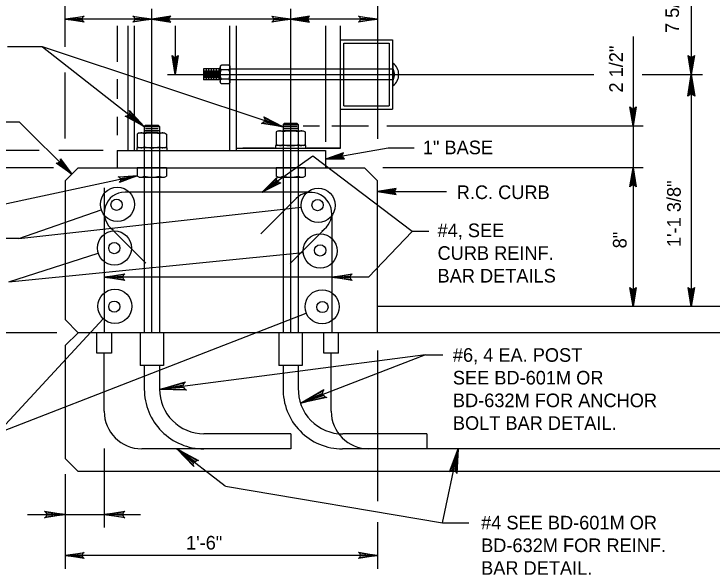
# Model space of a CAD drawing. Extents: x 641054 to 641910, y 298137 to 299325.
# Drawn here: x 641174.5 to 641328.5, y 298785.6 to 298908.1 of the extents above; entities that cross this region are included whole.
import ezdxf

# ---------------------------------------------------------------- set-up
doc = ezdxf.new("R2010")
doc.units = 0
for name, color, linetype in [('1', 7, 'Continuous'), ('2', 7, 'Continuous'), ('3', 7, 'Continuous'), ('4', 7, 'Continuous'), ('S-STEL', 7, 'Continuous')]:
    doc.layers.add(name, color=color, linetype=linetype)

msp = doc.modelspace()

# ---------------------------------------------------------------- linework, layer by layer
at = {"layer": '1'}
for p, q in [((641323.89, 298981.43), (641323.89, 298843.61)), ((641185.81, 298900.89), (641185.81, 298948.15)), ((641254.66, 298939.43), (641254.66, 298880.61)), ((641254.66, 298906.98), (641185.81, 298906.98)), ((641197.28, 298905.47), (641197.28, 298897.55)), ((641210.04, 298905.47), (641210.04, 298894.7)), ((641243.19, 298905.47), (641243.19, 298879.92)), ((641311.04, 298903.12), (641311.04, 298868.53)), ((641180.8, 298900.88), (641173.07, 298900.88)), ((641233.86, 298883.2), (641180.8, 298900.88)), ((641180.8, 298900.88), (641203.26, 298883.3)), ((641221.91, 298896.86), (641220.25, 298896.86)), ((641258.12, 298895.93), (641258.12, 298897.21)), ((641258.14, 298895.93), (641258.14, 298897.21)), ((641185.81, 298880.69), (641185.81, 298895.19)), ((641220.01, 298895.99), (641216.31, 298895.99)), ((641216.31, 298895.99), (641216.31, 298893.6)), ((641216.59, 298895.62), (641216.59, 298893.99)), ((641216.87, 298895.99), (641216.87, 298893.6)), ((641217.15, 298895.62), (641217.15, 298893.99)), ((641217.43, 298895.99), (641217.43, 298893.6)), ((641217.7, 298895.62), (641217.7, 298893.99)), ((641217.98, 298895.99), (641217.98, 298893.6)), ((641218.26, 298895.62), (641218.26, 298893.99)), ((641218.54, 298895.99), (641218.54, 298893.6)), ((641218.82, 298895.62), (641218.82, 298893.99)), ((641219.1, 298895.99), (641219.1, 298893.6)), ((641219.38, 298895.62), (641219.38, 298893.99)), ((641219.66, 298895.99), (641219.66, 298893.6)), ((641219.94, 298895.62), (641219.94, 298893.99)), ((641220.01, 298896.59), (641220.01, 298896.35)), ((641220.01, 298896.35), (641220.01, 298894.79)), ((641221.91, 298895.83), (641220.25, 298895.83)), ((641222.15, 298896.59), (641222.15, 298893)), ((641247.25, 298895.95), (641222.15, 298895.95)), ((641257.29, 298895.95), (641247.25, 298895.95)), ((641258.02, 298895.95), (641257.3, 298895.95)), ((641258.01, 298896.39), (641258.01, 298894.82)), ((641258.12, 298895.93), (641258.14, 298895.93)), ((641258.12, 298895.93), (641258.12, 298893.58)), ((641197.28, 298893.74), (641197.28, 298889.42)), ((641220.01, 298894.79), (641220.01, 298893.24)), ((641221.91, 298893.76), (641220.25, 298893.76)), ((641220.01, 298893.6), (641216.31, 298893.6)), ((641220.01, 298893.24), (641220.01, 298893)), ((641221.91, 298892.72), (641220.25, 298892.72)), ((641247.25, 298893.56), (641222.15, 298893.56)), ((641257.29, 298893.56), (641247.25, 298893.56)), ((641258.02, 298893.56), (641257.3, 298893.56)), ((641258.12, 298892.31), (641258.12, 298893.58)), ((641258.14, 298892.31), (641258.14, 298893.58)), ((641197.28, 298885.46), (641197.28, 298881.38)), ((641175.75, 298884.27), (641171.85, 298884.27)), ((641187.24, 298872.78), (641175.75, 298884.27)), ((641203.26, 298883.3), (641203.54, 298883.58)), ((641203.26, 298883.3), (641203.26, 298881.9)), ((641203.26, 298883.3), (641206.61, 298883.3)), ((641203.53, 298882.88), (641206.34, 298882.88)), ((641203.54, 298883.58), (641206.33, 298883.58)), ((641206.61, 298883.3), (641206.33, 298883.58)), ((641206.61, 298883.3), (641206.61, 298881.9)), ((641233.86, 298883.77), (641234.14, 298884.05)), ((641233.86, 298883.77), (641233.86, 298882.38)), ((641233.86, 298883.77), (641237.21, 298883.77)), ((641233.86, 298882.94), (641237.21, 298882.94)), ((641234.13, 298883.36), (641236.94, 298883.36)), ((641234.14, 298884.05), (641236.93, 298884.05)), ((641237.21, 298883.77), (641236.93, 298884.05)), ((641237.21, 298883.77), (641237.21, 298882.38)), ((641238.3, 298883.48), (641241.88, 298883.48)), ((641244.6, 298883.48), (641252.72, 298883.48)), ((641256.75, 298883.48), (641313.3, 298883.48)), ((641202.15, 298881.9), (641201.71, 298881.65)), ((641201.71, 298881.65), (641201.71, 298878.86)), ((641202.15, 298881.9), (641207.72, 298881.9)), ((641203.26, 298882.46), (641206.61, 298882.46)), ((641203.26, 298882.38), (641203.26, 298837.87)), ((641203.26, 298881.66), (641203.26, 298878.85)), ((641203.53, 298882.04), (641206.34, 298882.04)), ((641206.61, 298882.38), (641206.61, 298837.87)), ((641206.61, 298881.66), (641206.61, 298878.86)), ((641207.72, 298881.9), (641208.16, 298881.65)), ((641208.16, 298881.65), (641208.16, 298878.86)), ((641232.75, 298882.38), (641232.32, 298882.13)), ((641232.32, 298882.13), (641232.32, 298879.34)), ((641232.75, 298882.38), (641238.33, 298882.38)), ((641233.86, 298882.38), (641233.86, 298837.87)), ((641233.86, 298882.14), (641233.86, 298879.33)), ((641234.13, 298882.52), (641236.94, 298882.52)), ((641237.21, 298882.38), (641237.21, 298837.87)), ((641237.21, 298882.14), (641237.21, 298879.34)), ((641238.33, 298882.38), (641238.76, 298882.13)), ((641238.76, 298882.13), (641238.76, 298879.34)), ((641202.15, 298878.61), (641201.71, 298878.86)), ((641207.72, 298878.61), (641208.16, 298878.86)), ((641232.75, 298879.09), (641232.32, 298879.34)), ((641238.33, 298879.09), (641238.76, 298879.34)), ((641257.03, 298878.52), (641243.19, 298876.13)), ((641262.77, 298878.52), (641257.03, 298878.52)), ((641180.09, 298878.04), (641168.79, 298878.04)), ((641194.18, 298878.04), (641184.37, 298878.04)), ((641183.24, 298874.22), (641168.79, 298874.22)), ((641201.71, 298874.21), (641201.71, 298872.37)), ((641208.16, 298874.21), (641201.71, 298874.21)), ((641203.26, 298874.21), (641203.26, 298872.37)), ((641206.61, 298874.21), (641206.61, 298872.37)), ((641208.16, 298874.21), (641208.16, 298872.37)), ((641232.32, 298874.22), (641232.32, 298872.37)), ((641238.76, 298874.22), (641232.32, 298874.22)), ((641233.86, 298874.22), (641233.86, 298872.37)), ((641237.21, 298874.22), (641237.21, 298872.37)), ((641238.76, 298874.22), (641238.76, 298872.37)), ((641313.3, 298874.22), (641255.88, 298874.22)), ((641311.04, 298874.22), (641311.04, 298843.61)), ((641201.71, 298872.47), (641164.04, 298864.39)), ((641202.15, 298872.12), (641201.71, 298872.37)), ((641202.15, 298872.12), (641207.72, 298872.12)), ((641207.72, 298872.12), (641208.16, 298872.37)), ((641232.75, 298872.12), (641232.32, 298872.37)), ((641232.75, 298872.12), (641238.33, 298872.12)), ((641238.33, 298872.12), (641238.76, 298872.37)), ((641254.66, 298868.96), (641269.92, 298868.96)), ((641183.99, 298837.87), (641169.06, 298837.87)), ((641254.66, 298833.93), (641254.66, 298800.72)), ((641203.26, 298830.61), (641203.26, 298825.43)), ((641206.61, 298830.61), (641206.61, 298825.43)), ((641233.86, 298830.61), (641233.86, 298825.67)), ((641237.21, 298830.61), (641237.21, 298825.66)), ((641235.58, 298815.61), (641216.39, 298815.61)), ((641235.58, 298815.61), (641235.58, 298812.27)), ((641265.58, 298815.55), (641247.05, 298815.55)), ((641265.58, 298815.55), (641265.58, 298812.27)), ((641235.58, 298812.27), (641216.39, 298812.27)), ((641265.58, 298812.27), (641246.99, 298812.27)), ((641185.81, 298806.72), (641185.81, 298785.83)), ((641254.66, 298796.11), (641254.66, 298785.83)), ((641254.66, 298788.78), (641185.81, 298788.78))]:
    msp.add_line(p, q, dxfattribs=at)
msp.add_lwpolyline([(641323.32, 298890.23), (641323.65, 298890.4), (641323.89, 298894.78), (641323.32, 298890.23), (641323.12, 298890), (641323.89, 298894.78), (641324.11, 298890.41), (641324.44, 298890.25), (641323.89, 298894.78), (641324.65, 298890), (641324.44, 298890.25)], dxfattribs=at)
for points in [[(641208.28, 298878.04), (641208.28, 298878.61), (641201.59, 298878.61), (641201.59, 298878.04)], [(641238.89, 298878.52), (641238.89, 298879.09), (641232.19, 298879.09), (641232.19, 298878.52)]]:
    msp.add_lwpolyline(points, close=True, dxfattribs=at)
for centre, radius, start, end in [((641256.33, 298894.76), 3.04, 306.3703, 53.6297), ((641258, 298896.07), 0.119, 272.7217, 0.0027), ((641256.33, 298894.76), 2.15, 326.9318, 33.0682), ((641258, 298893.44), 0.119, 359.9973, 87.2783), ((641202.49, 298880.58), 1.33, 54.2974, 89.9999), ((641204.93, 298876.16), 5.75, 73.0653, 106.9335), ((641207.38, 298880.58), 1.33, 89.9993, 125.7017), ((641233.09, 298881.05), 1.33, 54.2974, 89.9999), ((641235.54, 298876.63), 5.75, 73.0653, 106.9335), ((641237.99, 298881.05), 1.33, 89.9993, 125.7017), ((641202.49, 298879.94), 1.33, 269.9985, 305.701), ((641204.93, 298884.36), 5.75, 253.0634, 286.9317), ((641207.38, 298879.94), 1.33, 234.2959, 269.9983), ((641233.09, 298880.42), 1.33, 269.9985, 305.701), ((641235.54, 298884.84), 5.75, 253.0634, 286.9317), ((641237.99, 298880.42), 1.33, 234.2959, 269.9983), ((641202.49, 298873.45), 1.33, 269.9985, 305.701), ((641204.93, 298877.87), 5.75, 253.0634, 286.9317), ((641207.38, 298873.45), 1.33, 234.2959, 269.9983), ((641233.09, 298873.45), 1.33, 269.9985, 305.701), ((641235.54, 298877.87), 5.75, 253.0634, 286.9317), ((641237.99, 298873.45), 1.33, 234.2959, 269.9983), ((641216.39, 298825.39), 13.13, 179.7931, 270), ((641216.39, 298825.39), 9.78, 179.7931, 270), ((641246.99, 298825.39), 13.13, 178.7837, 270), ((641247.05, 298825.39), 9.84, 178.4167, 270)]:
    msp.add_arc(centre, radius, start, end, dxfattribs=at)
for points, degree in [([(641220.01, 298896.35), (641220.02, 298896.42), (641220.04, 298896.58), (641220.15, 298896.74), (641220.23, 298896.83), (641220.25, 298896.86)], 3), ([(641220.01, 298896.59), (641220.25, 298896.86)], 1), ([(641222.15, 298896.35), (641222.14, 298896.42), (641222.12, 298896.58), (641222.01, 298896.74), (641221.93, 298896.83), (641221.91, 298896.86)], 3), ([(641221.91, 298896.86), (641222.15, 298896.59)], 1), ([(641220.25, 298895.83), (641220.19, 298895.91), (641220.07, 298896.06), (641220.01, 298896.25), (641220.01, 298896.34), (641220.01, 298896.35)], 3), ([(641220.01, 298894.79), (641220.01, 298894.82), (641220.02, 298894.97), (641220.05, 298895.26), (641220.15, 298895.58), (641220.23, 298895.77), (641220.25, 298895.83)], 3), ([(641221.91, 298895.83), (641221.97, 298895.91), (641222.09, 298896.06), (641222.15, 298896.25), (641222.15, 298896.34), (641222.15, 298896.35)], 3), ([(641222.15, 298894.79), (641222.15, 298894.82), (641222.15, 298894.97), (641222.11, 298895.26), (641222.01, 298895.58), (641221.94, 298895.77), (641221.91, 298895.83)], 3), ([(641222.15, 298895.99), (641222.15, 298895.99)], 1), ([(641258, 298895.95), (641258, 298895.95), (641258.03, 298895.95), (641258.1, 298895.94), (641258.11, 298895.89), (641258.12, 298895.87)], 3), ([(641258, 298895.95), (641258, 298895.95)], 1), ([(641220.25, 298893.76), (641220.22, 298893.84), (641220.13, 298894.05), (641220.04, 298894.4), (641220.02, 298894.66), (641220.01, 298894.79)], 3), ([(641220.01, 298893.24), (641220.02, 298893.31), (641220.04, 298893.47), (641220.15, 298893.64), (641220.23, 298893.73), (641220.25, 298893.76)], 3), ([(641221.91, 298893.76), (641221.95, 298893.84), (641222.03, 298894.05), (641222.13, 298894.4), (641222.14, 298894.66), (641222.15, 298894.79)], 3), ([(641222.15, 298893.24), (641222.14, 298893.31), (641222.12, 298893.47), (641222.01, 298893.64), (641221.93, 298893.73), (641221.91, 298893.76)], 3), ([(641258.12, 298893.65), (641258.11, 298893.63), (641258.1, 298893.58), (641258.03, 298893.56), (641258, 298893.56), (641258, 298893.56)], 3), ([(641220.25, 298892.72), (641220.19, 298892.8), (641220.07, 298892.95), (641220.01, 298893.14), (641220.01, 298893.24), (641220.01, 298893.24)], 3), ([(641220.25, 298892.72), (641220.01, 298893)], 1), ([(641221.91, 298892.72), (641221.97, 298892.8), (641222.09, 298892.95), (641222.15, 298893.14), (641222.15, 298893.24), (641222.15, 298893.24)], 3), ([(641222.15, 298893), (641221.91, 298892.72)], 1), ([(641222.15, 298893.6), (641222.15, 298893.6)], 1)]:
    msp.add_open_spline(points, degree=degree, dxfattribs=at)
at = {"layer": '2'}
for p, q in [((641204.93, 298837.87), (641204.93, 298909.25)), ((641235.54, 298837.87), (641235.54, 298909.25)), ((641199.67, 298878.04), (641199.67, 298905.47)), ((641201.11, 298878.04), (641201.11, 298905.47)), ((641222.14, 298878.04), (641222.14, 298905.47)), ((641223.58, 298878.04), (641223.58, 298905.47)), ((641246.53, 298878.52), (641246.53, 298905.47)), ((641246.53, 298902.42), (641258.01, 298902.42)), ((641247.25, 298887.84), (641247.25, 298901.71)), ((641247.25, 298901.71), (641257.29, 298901.71)), ((641257.29, 298901.71), (641257.29, 298887.84)), ((641258.01, 298902.42), (641258.01, 298887.12)), ((641208.34, 298894.78), (641302.41, 298894.78)), ((641313.04, 298894.78), (641326.35, 298894.78)), ((641247.25, 298887.84), (641257.29, 298887.84)), ((641246.53, 298887.12), (641258.01, 298887.12)), ((641223.58, 298878.52), (641246.53, 298878.52)), ((641246.53, 298878.52), (641239.12, 298878.52)), ((641197.28, 298878.04), (641243.19, 298878.04)), ((641197.28, 298878.04), (641197.28, 298874.22)), ((641243.19, 298878.04), (641243.19, 298874.22)), ((641185.81, 298871.35), (641188.68, 298874.22)), ((641188.68, 298874.22), (641251.8, 298874.22)), ((641254.66, 298871.35), (641251.8, 298874.22)), ((641185.81, 298871.35), (641185.81, 298840.74)), ((641254.66, 298837.87), (641254.66, 298871.35)), ((641175.55, 298858.64), (641237.87, 298865.52)), ((641175.55, 298858.64), (641193.76, 298864.92)), ((641252.67, 298850.1), (641262.33, 298860.18)), ((641265.99, 298860.18), (641262.33, 298860.18)), ((641175.55, 298858.64), (641169.48, 298858.64)), ((641173.4, 298849.09), (641238.3, 298855.51)), ((641173.4, 298849.09), (641193.08, 298855.38)), ((641252.67, 298850.1), (641194.42, 298850.1)), ((641369.97, 298843.61), (641254.66, 298843.61)), ((641170.83, 298815.69), (641238.97, 298842.2)), ((641170.83, 298815.69), (641194.22, 298840.92)), ((641188.68, 298837.87), (641185.81, 298840.74)), ((641185.81, 298835.01), (641188.68, 298837.87)), ((641369.97, 298837.87), (641188.68, 298837.87)), ((641202.32, 298837.87), (641202.32, 298830.61)), ((641207.48, 298837.87), (641202.32, 298837.87)), ((641207.48, 298837.87), (641207.48, 298830.61)), ((641232.93, 298837.87), (641232.93, 298830.61)), ((641238.08, 298837.87), (641232.93, 298837.87)), ((641238.08, 298837.87), (641238.08, 298830.61)), ((641185.81, 298835.01), (641185.81, 298810.14)), ((641265.24, 298832.95), (641206.61, 298825.36)), ((641265.24, 298832.95), (641237.7, 298822.32)), ((641265.24, 298832.95), (641269.1, 298832.95)), ((641207.48, 298830.61), (641202.32, 298830.61)), ((641238.08, 298830.61), (641232.93, 298830.61)), ((641194.42, 298812.35), (641194.42, 298794.92)), ((641221.11, 298804.05), (641210.4, 298812.27)), ((641269, 298795.95), (641272.48, 298812.27)), ((641188.68, 298807.27), (641185.81, 298810.14)), ((641369.97, 298807.27), (641188.68, 298807.27)), ((641177.47, 298797.78), (641185.81, 298797.78)), ((641185.81, 298797.78), (641194.42, 298797.78)), ((641194.42, 298797.78), (641202.42, 298797.78))]:
    msp.add_line(p, q, dxfattribs=at)
for points in [[(641189.78, 298906.49), (641189.63, 298906.77), (641185.81, 298906.98), (641189.78, 298906.49), (641189.98, 298906.31), (641185.81, 298906.98), (641189.63, 298907.17), (641189.77, 298907.46), (641185.81, 298906.98), (641189.98, 298907.65), (641189.77, 298907.46)], [(641200.96, 298907.48), (641201.11, 298907.2), (641204.93, 298906.98), (641200.96, 298907.48), (641200.76, 298907.66), (641204.93, 298906.98), (641201.11, 298906.8), (641200.97, 298906.51), (641204.93, 298906.98), (641200.76, 298906.32), (641200.97, 298906.51)], [(641208.91, 298907.48), (641208.76, 298907.2), (641204.93, 298906.98), (641208.91, 298907.48), (641209.11, 298907.66), (641204.93, 298906.98), (641208.76, 298906.8), (641208.9, 298906.51), (641204.93, 298906.98), (641209.11, 298906.32), (641208.9, 298906.51)], [(641231.56, 298907.48), (641231.71, 298907.2), (641235.54, 298906.98), (641231.56, 298907.48), (641231.36, 298907.66), (641235.54, 298906.98), (641231.72, 298906.8), (641231.58, 298906.51), (641235.54, 298906.98), (641231.36, 298906.32), (641231.58, 298906.51)], [(641239.51, 298907.48), (641239.36, 298907.2), (641235.54, 298906.98), (641239.51, 298907.48), (641239.71, 298907.66), (641235.54, 298906.98), (641239.36, 298906.8), (641239.5, 298906.51), (641235.54, 298906.98), (641239.71, 298906.32), (641239.5, 298906.51)], [(641250.69, 298907.48), (641250.84, 298907.2), (641254.66, 298906.98), (641250.69, 298907.48), (641250.49, 298907.66), (641254.66, 298906.98), (641250.84, 298906.8), (641250.7, 298906.51), (641254.66, 298906.98), (641250.49, 298906.32), (641250.7, 298906.51)], [(641210.54, 298898.75), (641210.25, 298898.6), (641210.04, 298894.78), (641210.54, 298898.75), (641210.71, 298898.95), (641210.04, 298894.78), (641209.85, 298898.6), (641209.57, 298898.74), (641210.04, 298894.78), (641209.38, 298898.95), (641209.57, 298898.74)], [(641324.39, 298898.75), (641324.11, 298898.6), (641323.89, 298894.78), (641324.39, 298898.75), (641324.57, 298898.95), (641323.89, 298894.78), (641323.71, 298898.6), (641323.42, 298898.74), (641323.89, 298894.78), (641323.23, 298898.95), (641323.42, 298898.74)], [(641311.54, 298887.45), (641311.25, 298887.3), (641311.04, 298883.48), (641311.54, 298887.45), (641311.71, 298887.66), (641311.04, 298883.48), (641310.85, 298887.3), (641310.57, 298887.44), (641311.04, 298883.48), (641310.37, 298887.66), (641310.57, 298887.44)], [(641200.05, 298886.51), (641199.99, 298886.15), (641203.26, 298883.3), (641200.05, 298886.51), (641199.99, 298886.81), (641203.26, 298883.3), (641199.71, 298885.79), (641199.39, 298885.63), (641203.26, 298883.3), (641199.06, 298885.61), (641199.39, 298885.63)], [(641229.77, 298885.16), (641229.83, 298884.8), (641233.86, 298883.2), (641229.77, 298885.16), (641229.61, 298885.42), (641233.86, 298883.2), (641229.69, 298884.37), (641229.43, 298884.11), (641233.86, 298883.2), (641229.14, 298883.98), (641229.43, 298884.11)], [(641262.33, 298860.18), (641240.41, 298876.78), (641229.24, 298868.86)], [(641247.02, 298877.3), (641246.92, 298876.99), (641243.19, 298876.13), (641247.02, 298877.3), (641247.19, 298877.5), (641243.19, 298876.13), (641246.99, 298876.59), (641247.17, 298876.34), (641243.19, 298876.13), (641247.42, 298876.18), (641247.17, 298876.34)], [(641184.78, 298875.94), (641184.69, 298875.63), (641187.24, 298872.78), (641184.78, 298875.94), (641184.76, 298876.21), (641187.24, 298872.78), (641184.41, 298875.35), (641184.11, 298875.25), (641187.24, 298872.78), (641183.82, 298875.26), (641184.11, 298875.25)], [(641310.54, 298870.24), (641310.83, 298870.39), (641311.04, 298874.22), (641310.54, 298870.24), (641310.37, 298870.04), (641311.04, 298874.22), (641311.23, 298870.39), (641311.51, 298870.25), (641311.04, 298874.22), (641311.7, 298870.04), (641311.51, 298870.25)], [(641197.72, 298872.12), (641197.93, 298871.87), (641201.71, 298872.47), (641197.72, 298872.12), (641197.49, 298872.25), (641201.71, 298872.47), (641198.02, 298871.48), (641197.94, 298871.17), (641201.71, 298872.47), (641197.77, 298870.94), (641197.94, 298871.17)], [(641233.06, 298870.93), (641232.75, 298871.09), (641229.24, 298868.86), (641233.06, 298870.93), (641233.35, 298870.91), (641229.24, 298868.86), (641232.5, 298871.44), (641232.44, 298871.78), (641229.24, 298868.86), (641232.51, 298872.09), (641232.44, 298871.78)], [(641258.64, 298869.46), (641258.49, 298869.17), (641254.66, 298868.96), (641258.64, 298869.46), (641258.84, 298869.63), (641254.66, 298868.96), (641258.49, 298868.77), (641258.63, 298868.48), (641254.66, 298868.96), (641258.84, 298868.29), (641258.63, 298868.48)], [(641198.73, 298849.56), (641198.57, 298849.87), (641194.42, 298850.1), (641198.73, 298849.56), (641198.95, 298849.37), (641194.42, 298850.1), (641198.56, 298850.31), (641198.72, 298850.62), (641194.42, 298850.1), (641198.95, 298850.82), (641198.72, 298850.62)], [(641248.91, 298849.56), (641248.75, 298849.87), (641244.6, 298850.1), (641248.91, 298849.56), (641249.13, 298849.37), (641244.6, 298850.1), (641248.75, 298850.31), (641248.9, 298850.62), (641244.6, 298850.1), (641249.13, 298850.82), (641248.9, 298850.62)], [(641311.54, 298847.59), (641311.25, 298847.44), (641311.04, 298843.61), (641311.54, 298847.59), (641311.71, 298847.79), (641311.04, 298843.61), (641310.85, 298847.43), (641310.57, 298847.57), (641311.04, 298843.61), (641310.37, 298847.79), (641310.57, 298847.57)], [(641324.39, 298847.59), (641324.11, 298847.44), (641323.89, 298843.61), (641324.39, 298847.59), (641324.57, 298847.79), (641323.89, 298843.61), (641323.71, 298847.43), (641323.42, 298847.57), (641323.89, 298843.61), (641323.23, 298847.79), (641323.42, 298847.57)], [(641212.26, 298825.4), (641212, 298825.78), (641206.61, 298825.36), (641212.26, 298825.4), (641212.58, 298825.2), (641206.61, 298825.36), (641211.92, 298826.34), (641212.06, 298826.76), (641206.61, 298825.36), (641212.33, 298827.07), (641212.06, 298826.76)], [(641243.18, 298823.71), (641242.84, 298824.01), (641237.7, 298822.32), (641243.18, 298823.71), (641243.54, 298823.58), (641237.7, 298822.32), (641242.63, 298824.53), (641242.66, 298824.98), (641237.7, 298822.32), (641242.85, 298825.34), (641242.66, 298824.98)], [(641214.07, 298808.68), (641214.14, 298809.08), (641210.4, 298812.27), (641214.07, 298808.68), (641214.15, 298808.34), (641210.4, 298812.27), (641214.45, 298809.5), (641214.81, 298809.68), (641210.4, 298812.27), (641215.18, 298809.71), (641214.81, 298809.68)], [(641270.81, 298807.41), (641271.21, 298807.52), (641272.48, 298812.27), (641270.81, 298807.41), (641270.54, 298807.2), (641272.48, 298812.27), (641271.72, 298807.42), (641272.04, 298807.17), (641272.48, 298812.27), (641272.22, 298806.85), (641272.04, 298807.17)], [(641221.17, 298804.05), (641269, 298795.95), (641274.81, 298795.95)], [(641181.49, 298798.33), (641181.65, 298798.01), (641185.81, 298797.78), (641181.49, 298798.33), (641181.27, 298798.51), (641185.81, 298797.78), (641181.66, 298797.58), (641181.51, 298797.27), (641185.81, 298797.78), (641181.27, 298797.06), (641181.51, 298797.27)], [(641198.73, 298797.24), (641198.57, 298797.55), (641194.42, 298797.78), (641198.73, 298797.24), (641198.95, 298797.05), (641194.42, 298797.78), (641198.56, 298797.99), (641198.72, 298798.3), (641194.42, 298797.78), (641198.95, 298798.5), (641198.72, 298798.3)], [(641189.78, 298788.29), (641189.63, 298788.57), (641185.81, 298788.78), (641189.78, 298788.29), (641189.98, 298788.11), (641185.81, 298788.78), (641189.63, 298788.97), (641189.77, 298789.26), (641185.81, 298788.78), (641189.98, 298789.45), (641189.77, 298789.26)], [(641250.69, 298789.28), (641250.84, 298789), (641254.66, 298788.78), (641250.69, 298789.28), (641250.49, 298789.46), (641254.66, 298788.78), (641250.84, 298788.6), (641250.7, 298788.31), (641254.66, 298788.78), (641250.49, 298788.12), (641250.7, 298788.31)]]:
    msp.add_lwpolyline(points, dxfattribs=at)
for centre in [(641197.32, 298866.15), (641241.61, 298865.93), (641196.67, 298856.53), (641242.04, 298855.88), (641196.78, 298843.68), (641242.47, 298843.57)]:
    msp.add_circle(centre, 3.76, dxfattribs=at)
at = {"layer": '3'}
msp.add_line((641251.8, 298874.22), (641251.8, 298874.22), dxfattribs=at)
at = {"layer": '4'}
for p, q in [((641194.42, 298869.78), (641194.42, 298837.93)), ((641239.31, 298868.86), (641199.01, 298868.86)), ((641228.95, 298859.63), (641236.75, 298867.43)), ((641244.6, 298864.18), (641244.6, 298837.93)), ((641203.56, 298853.22), (641196.51, 298860.26)), ((641235.45, 298853.13), (641242.72, 298860.39)), ((641192.81, 298833.34), (641192.81, 298837.93)), ((641196.02, 298837.93), (641196.02, 298833.34)), ((641242.87, 298833.34), (641242.87, 298837.93)), ((641246.09, 298833.34), (641246.09, 298837.93)), ((641196.02, 298833.34), (641192.81, 298833.34)), ((641194.42, 298820.54), (641194.42, 298833.34)), ((641246.09, 298833.34), (641242.87, 298833.34)), ((641244.48, 298820.54), (641244.48, 298833.34)), ((641224.75, 298812.27), (641202.69, 298812.27)), ((641344.66, 298812.27), (641252.75, 298812.27))]:
    msp.add_line(p, q, dxfattribs=at)
for centre in [(641197.15, 298866.07), (641241.47, 298865.99), (641196.64, 298856.52), (641242.04, 298855.99), (641196.64, 298843.61), (641242.55, 298843.52)]:
    msp.add_circle(centre, 1.24, dxfattribs=at)
for centre, radius, start, end in [((641199.01, 298864.26), 4.6, 90, 236.2417), ((641240, 298864.18), 4.6, 301.7171, 135), ((641202.69, 298820.54), 8.27, 180, 270), ((641252.75, 298820.54), 8.27, 180, 270)]:
    msp.add_arc(centre, radius, start, end, dxfattribs=at)
at = {"layer": 'S-STEL'}
for p, q in [((641258.02, 298893.56), (641257.3, 298893.56)), ((641231.95, 298878.52), (641225.02, 298878.52))]:
    msp.add_line(p, q, dxfattribs=at)

# ---------------------------------------------------------------- texts
at = {"layer": '2'}
for s, p in [('7 5/8"', (641321.18, 298903.91)), ('2 1/2"', (641308.81, 298890.79)), ('1\'-1 3/8"', (641321.56, 298856.74)), ('8"', (641309.62, 298856.45))]:
    msp.add_text(s, height=3, rotation=90, dxfattribs=at).set_placement(p)
for s, height, p in [('1" BASE  ', 3, (641264.69, 298877.2)), ('R.C. CURB', 3, (641272.16, 298867.32)), ('#4, SEE', 3, (641267.93, 298858.92)), ('CURB REINF.', 3, (641267.93, 298853.92)), ('BAR DETAILS', 3, (641267.93, 298848.92)), ('#6, 4 EA. POST', 3.0001, (641271.31, 298831.45)), ('SEE BD-601M OR', 3.0001, (641271.31, 298826.45)), ('BD-632M FOR ANCHOR', 3.0001, (641271.31, 298821.45)), ('BOLT BAR DETAIL.', 3.0001, (641271.31, 298816.45)), ('#4 SEE BD-601M OR', 3.0001, (641277.54, 298794.51)), ('1\'-6"', 3, (641212.46, 298790.08)), ('BD-632M FOR REINF.', 3.0001, (641277.54, 298789.51)), ('BAR DETAIL.', 3.0001, (641277.54, 298784.51))]:
    msp.add_text(s, height=height, dxfattribs=at).set_placement(p)

doc.saveas('drawing.dxf')
